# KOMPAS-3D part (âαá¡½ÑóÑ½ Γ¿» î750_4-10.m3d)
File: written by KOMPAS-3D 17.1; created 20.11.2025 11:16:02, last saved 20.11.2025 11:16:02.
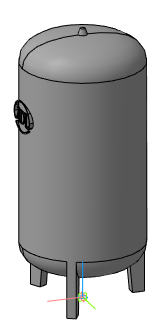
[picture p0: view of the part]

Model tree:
1. Операция без истории:2

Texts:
  REVIT MATERIAL OVERRIDDEN
  REVIT MATERIAL ID
  REVIT SUBCATEGORY ID
  REVIT CATEGORY ID
  REVIT ELEMENT ID
  REVIT BREP TAG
